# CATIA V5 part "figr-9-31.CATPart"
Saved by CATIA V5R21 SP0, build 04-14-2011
Part number: Part1
Bounding box of the stored display mesh (mm): x -40 to 40, y -41.231 to 41.231, z -41.231 to 41.225
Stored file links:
  D:\CATIA V5R21 E-RESOURCES\CATIA-V5R21\catia-v5r21-prt\c09-catia-v5r20-prt\c09-catia-v5r21-figr-9-31.CATPart
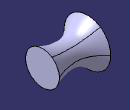
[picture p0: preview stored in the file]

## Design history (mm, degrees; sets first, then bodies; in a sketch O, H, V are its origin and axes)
Body1 (main body)
  Sketch1 on yz-plane, origin (0, 0, 0), H (0, 1, 0), V (0, 0, 1)
    circle A1 centre (0, 0) radius 20
  Plane1: type Offset, RefPlane yz-plane, Offset 40
  Plane2: type Offset, RefPlane yz-plane, Offset -40
  Sketch2 on Plane1, origin (40, 0, 0), H (0, 1, 0), V (0, 0, 1)
    circle A1 centre (0, 0) radius 30
  Sketch3 on Plane2, origin (-40, 0, 0), H (0, 1, 0), V (0, 0, 1)
    circle A1 centre (0, 0) radius 41.2311
  Loft1: solid, Sections (Sketch2; Sketch1; Sketch3)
